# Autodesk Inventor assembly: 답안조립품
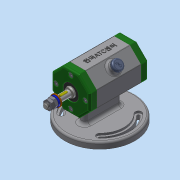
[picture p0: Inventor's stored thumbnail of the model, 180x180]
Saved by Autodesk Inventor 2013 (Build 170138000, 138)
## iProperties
Created: 2017-06
Part Number: 답안조립품
Document SubType Name: Assembly
Designer: Administrator
Author: Administrator
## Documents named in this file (14)
- C:\Users\Administrator\Desktop\470607V1002\답안조립품.iam
- C:\Users\Administrator\Desktop\470607V1002\V벨트풀리.ipt
- C:\Users\Administrator\Desktop\470607V1002\고무캡.ipt
- C:\Users\Administrator\Desktop\470607V1002\너트 M 8.ipt
- C:\Users\Administrator\Desktop\470607V1002\뒤커버.ipt
- C:\Users\Administrator\Desktop\470607V1002\베어링 15 x 32 x 9.ipt
- C:\Users\Administrator\Desktop\470607V1002\본체.ipt
- C:\Users\Administrator\Desktop\470607V1002\볼트 M4 x 12.ipt
- C:\Users\Administrator\Desktop\470607V1002\스프링와셔 8.ipt
- C:\Users\Administrator\Desktop\470607V1002\앞커버.ipt
- C:\Users\Administrator\Desktop\470607V1002\오일 실 15 25 7.ipt
- C:\Users\Administrator\Desktop\470607V1002\와셔 8x17.ipt
- C:\Users\Administrator\Desktop\470607V1002\축.ipt
- C:\Users\Administrator\Desktop\470607V1002\키 3 x 3 x 12.ipt
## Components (2 placed, 2 different names)
1. V벨트풀리:1
2. 고무캡:1
